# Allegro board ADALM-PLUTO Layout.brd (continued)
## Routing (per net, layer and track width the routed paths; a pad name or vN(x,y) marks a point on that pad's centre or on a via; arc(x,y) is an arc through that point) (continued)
PGND: length 9.8
  TOP w0.305: 102.27,48.02 C181.1 ; C181.1 102.27,49.41 ; C181.1 101.63,48.71 ; 102.46,51.57 D2.2
  TOP w0.406: 102.97,50.87 103.24,51.15 P3.5
  TOP w0.508: 99.2,48.02 E10.2 ; E10.2 100.18,48.87 ; E10.2 101.15,48.02 ; 99.32,51.93 C214.2 100.18,51.13
  TOP w0.635: R58.2 103.1,47.32
  vias: v1(98.02,51.76) v1(98.91,48.89) v1(99.41,50.75) v1(100.81,50.75) v1(101.34,49.2) v1(102.33,50.87) v1(102.72,47.7) v1(103.6,55.06)
VCCPINT: length 38.6
  TOP w0.305: U4.G6 v2(54.73,35.35) ; U4.H5 v2(54.73,36.15) ; 77.95,13.92 UNK1P0V.1 ; UNK1P0V.1 77.95,15.44 ; UNK1P0V.1 77.19,14.68 ; UNK1P0V.1 78.71,14.68 ; U4.E10 v2(57.13,31.35) ; U4.G10 v2(55.53,31.35) ; U4.K5 v2(52.33,36.15) ; U4.F9 v2(56.33,32.15) ; U4.L10 v2(51.53,31.35) ; U4.J10 v2(53.13,31.35)
  TOP w0.508: 56.43,22.69 C68.1 56.99,22.13
  TOP w0.762: 78.62,17.79 C19.1 77.57,16.89 ; 81.6,17.79 C17.1 ; C17.1 83.7,17.79 ; C17.1 82.65,16.89 ; C71.1 59.9,22.55 ; C71.1 58.65,23.61 ; C71.1 57.39,22.55 ; C64.1 63.16,22.49 ; C64.1 60.64,22.49 ; C64.1 61.9,23.54 ; 85.19,16.89 C21.1 ; C21.1 84.14,17.79 ; C21.1 86.24,17.79 ; 80.11,16.89 C20.1 ; C20.1 81.16,17.79 ; C20.1 79.06,17.79
  TOP w1.524: 85,14.04 L4.2 85.99,16.14
  BOTTOM w0.305: v1(82.52,16.46) 84.03,16.46 R7.2
  BOTTOM w0.406: C72.1 51.53,31.84 v2(51.53,31.35) ; v2(55.53,31.35) 55.53,31.85 C74.1 55.73,32.05 56.23,32.05 v2(56.33,32.15) 56.33,32.76 C75.1 ; C70.1 54.73,35.35 v2(54.73,35.35) 54.73,36.15 v2(54.73,36.15) ; C66.1 53.83,30.64 v2(53.13,31.35) ; C73.1 52.33,36.15 v2(52.33,36.15)
  vias: v1(57.2,22.87) v1(57.2,22.11) v1(60.25,22.87) v1(60.25,22.11) v1(63.42,22.87) v1(63.42,22.11) v1(77.95,16.46) v1(77.95,15.69) v1(78.71,16.46) v1(78.71,15.69) v1(79.47,16.46) v1(79.47,15.69) v1(80.24,16.46) v1(80.24,15.69) v1(81,16.46) v1(81,15.69) v1(81.76,16.46) v1(81.76,15.69) v1(82.52,15.69)
VCCPLL: length 18.1
  TOP w0.305: U4.F5 v2(56.33,36.15)
  BOTTOM w0.152: 58.73,36.15 58.34,35.75 56.73,35.75 56.34,36.15 v2(56.33,36.15) 56.33,36.15 56.73,36.55 58.33,36.55 58.73,36.15
  BOTTOM w0.508: 58.73,36.15 C178.1 59.54,36.25 60.63,36.25 61.14,36.75 61.14,37.15 61.74,37.75 62.44,37.75 62.74,37.45
  BOTTOM w0.635: 62.74,37.45 65.28,37.45 C85.1 65.89,37.55 67.54,37.55 68.29,36.8 E1.2
VDD33_USB: length 3
  TOP w0.305: v1(80.36,25.35) 79.73,25.35 79.6,25.48 U15.20
  BOTTOM w0.508: v1(80.36,25.35) 79.86,24.84 C165.1
VDD_INTERFACE: length 10.2
  TOP w0.305: C33.1 32.29,16.08 C32.1 ; C33.1 32.7,17.09 ; C33.1 32.29,17.55 ; U5.H12 28.74,27.23 v2(28.83,27.14) 28.84,27.13 C43.1 C45.1
  TOP w0.635: E4.2 34.23,14 ; E4.2 32.27,14 ; E4.2 33.25,14.86 ; 33.06,15.95 C32.1 32.42,15.25
  BOTTOM w0.305: C44.1 28.83,27.26 28.83,27.26 v2(28.83,27.14) 28.83,26.65 C38.1
  vias: v1(32.99,16.84) v1(33.37,15.95) v1(33.37,15.31) v1(33.63,16.84) v1(34.01,15.95) v1(34.01,15.31) v1(34.26,16.84)
VDDA1P1_RX_VCO: length 3.1
  TOP w0.305: U5.G3 v2(29.14,35.28) ; U5.G2 v2(29.14,36.08)
  BOTTOM w0.305: v2(29.15,35.28) C125.2 29.63,35.94 R51.2 29.73,36.08 v2(29.14,36.08)
VIN: length 59.9
  TOP w0.152: U6.28 v2(91.8,40.71)
  TOP w0.203: U14.10 40.72,58.56 ; R222.1 41.06,60.41 40.79,60.68 39.17,60.68 38.92,60.44 R221.1
  TOP w0.254: 91.79,48.84 92.68,48.84 93.19,48.33 93.57,48.33
  TOP w0.305: 91.16,16.55 C8.1 91.62,16.14 ; 93.29,64.45 U8.9 93.7,63.86 ; 91.75,19.16 U3.13 92.5,19.6 ; U15.21 v1(79.86,25.98) 80.8,25.98 C164.1 ; R221.1 38.92,58.48 v1(38.96,58.44) 39.08,58.56 C62.2 40.72,58.56 ; 89.76,41.48 90.02,41.73 90.21,41.73 U6.25 90.3,41.12 ; 91.19,18.6 U3.12 90.76,17.85 ; 90.29,64.46 U8.15 ; U6.15 90.8,47.42 ; 90.8,41.12 U6.26 ; 89.78,47.04 89.98,46.84 90.18,46.84 U6.16 90.3,47.42 ; U6.27 91.3,40.98 v1(91.03,40.71) ; 92.99,19.57 R1.2 ; R1.2 93.9,19.57 ; R1.2 93.44,19.16 ; 93.57,48.33 94.65,48.33 R56.1 ; 89.29,63.86 U8.16 89.79,64.46 ; C169.1 51.41,12.65 ; C169.1 50.87,13.16 ; C169.1 50.87,12.14 ; 91.3,47.56 U6.14 ; U8.10 92.79,64.44
  TOP w0.508: C185.1 84.17,64.54 ; C185.1 83.12,63.64 ; C185.1 85.23,63.64 ; DS1.A v1(106.78,19.29) ; C184.1 87.9,63.64 ; C184.1 85.79,63.64 ; C184.1 86.84,64.54 ; DS2.A v1(106.91,10.91)
  TOP w0.635: 91.98,16.39 C9.1 ; C9.1 92.68,17.03 ; C9.1 93.38,16.39
  TOP w0.762: C138.1 89.95,51.32 ; C138.1 89.95,49.92 ; C138.1 90.59,50.62 ; C137.1 90.21,38.62 ; C137.1 90.84,37.92 ; C137.1 90.21,37.22 ; 89.95,48.14 C136.1 ; C136.1 90.59,48.84 ; C136.1 89.95,49.54 ; 90.21,39 C135.1 ; C135.1 90.84,39.7 ; C135.1 90.21,40.4 ; 52.8,12.85 E2.1
  TOP w1.016: 94.97,17.55 C11.1 93.91,16.65
  BOTTOM w0.254: U9.10 66.46,58.12 C188.1 C215.1
  BOTTOM w0.305: 28.24,13.55 E7.1 29.22,12.7 ; v1(68.17,55.19) 66.46,56.91 C215.1 ; R6.1 v1(92.94,18.11) ; 28.75,14.2 C123.1 28.21,13.69
  BOTTOM w0.406: R59.2 92.42,38.94 v1(91.67,38.94)
  vias: v1(29.18,13.79) v1(29.56,13.03) v1(52.04,12.52) v1(52.04,11.76) v1(52.93,12.52) v1(52.93,11.76) v1(83.35,64.94) v1(83.67,65.35) v1(83.98,64.94) v1(84.3,65.35) v1(84.62,64.94) v1(84.94,65.35) v1(85.25,64.94) v1(85.57,65.35) v1(85.89,64.94) v1(86.21,65.35) v1(86.52,64.94) v1(86.84,65.35) v1(87.16,64.94) v1(87.48,65.35) v1(87.79,64.94) v1(90.4,51.51) v1(90.4,37.03) v1(90.4,36.4) v1(90.78,50.87) v1(90.78,50.24) v1(90.78,49.6) v1(91.03,38.94) v1(91.03,38.3) v1(91.03,37.67) v1(91.03,37.03) v1(91.03,36.4) v1(91.03,17.47) v1(91.03,16.84) v1(91.41,50.87) v1(91.41,50.24) v1(91.41,49.6) v1(91.67,38.3) v1(91.67,37.67) v1(91.67,37.03) v1(91.67,36.4) v1(91.67,17.47) v1(91.67,16.84) v1(92.3,18.11) v1(92.3,17.47) v1(92.94,17.47) v1(93.57,18.11) v1(93.57,17.47) v1(94.21,18.11) v1(94.84,18.11)
VIN_5V_USB_DATA: length 12.2
  TOP w0.305: 93.06,60.14 92.99,60.22 92.79,60.7 U8.7 ; C210.1 96.33,60.94 ; C210.1 94.63,60.94 ; C210.1 95.48,60.14 ; 93.29,60.43 U8.8 93.92,61
  TOP w0.508: 103.1,41.22 F1.2 102.57,40.61
  TOP w0.635: E3.1 102.46,39.87 ; E3.1 103.44,39.02 ; E3.1 102.3,39.19 100.65,39.19 C183.1
  BOTTOM w0.406: v1(103.75,40.72) v1(103.75,40.09) 103.64,40.21 R88.1
  vias: v1(97.07,61.06) v1(97.07,60.43) v1(97.7,61.06) v1(97.7,60.43) v1(98.34,61.06) v1(98.34,60.43) v1(103.72,38.83) v1(103.75,41.36) v1(103.75,39.45) v1(104.39,41.36) v1(104.39,40.72) v1(104.39,40.09) v1(104.39,39.45) v1(104.36,38.83)
VIN_5V_USB_POWER: length 27.9
  TOP w0.254: 102.08,42.37 U16.A1 102.46,42.75
  TOP w0.305: 89.38,61 U8.1 89.79,60.42 ; 104.18,42.55 C182.1 ; C182.1 104.18,43.95 ; C182.1 103.54,43.25 ; 90.02,60.27 90.29,60.55 U8.2
  TOP w0.635: C209.1 89.09,59.98 ; C209.1 89.09,58.28 ; C209.1 89.89,59.13 ; 89.09,57.95 C212.1 89.89,57.1 ; 90.82,57.18 E9.1 ; E9.1 91.79,58.04 ; E9.1 92.77,57.18
  BOTTOM w0.305: v1(85.44,56.21) 84.05,57.6 74.52,57.6 73.9,56.98 R80.1 ; R70.1 89.76,59.59 v1(90.32,59.03)
  vias: v1(90.32,58.39) v1(90.96,59.03) v1(90.96,58.39) v1(91.59,59.03) v1(91.59,58.39) v1(102.97,45.16) v1(102.97,44.27) v1(103.6,45.16) v1(103.6,44.27) v1(104.24,45.16) v1(104.24,44.27)
1P3_SUPPLY_A: length 79.2
  TOP w0.203: U7.9 42.22,14.51 42.06,14.68 41.69,14.68 41.57,14.56
  TOP w0.305: U7.13 39.35,13.29 ; U7.13 38.57,12.86 ; U7.13 U7.14 38.57,12.21 ; U5.F2 v2(30.74,36.08) ; U5.E2 v2(31.54,36.08) ; U5.B10 v2(33.94,28.88) ; U5.B9 v2(33.94,29.68) ; C18.1 41.96,16.14 ; C18.1 41.04,16.14 ; C18.1 41.5,15.73 ; 40.23,15.73 C16.1 ; C16.1 39.77,16.14 ; C16.1 40.69,16.14 ; 42.39,16.33 UNK1P3V_A.1 43.15,15.57 ; U7.12 40.27,14.56 ; U7.12 U7.11 ; U7.12 39.84,13.78 ; 41.57,14.56 U7.10 U7.11 ; U7.11 40.92,14.56 ; U5.J3 v2(27.55,35.28) ; U5.K3 v2(26.74,35.28)
  TOP w0.635: 38.01,15.81 C14.1 ; C14.1 39.41,15.81 ; C14.1 38.71,15.17 ; 37.88,13.6 C15.1 ; C15.1 37.88,15 ; C15.1 38.52,14.3
  BOTTOM w0.305: 31.46,36.08 v2(30.74,36.08) ; 31.46,36.08 31.33,36.2 C23.1 31.33,36.96 31.84,37.47 C28.1 ; 31.46,36.08 v2(31.54,36.08) ; v2(27.55,35.28) 27.33,35.5 C39.1 27.33,36.46 27.45,36.58 ; v2(33.94,28.88) 33.86,28.96 C40.1 33.86,29.6 v2(33.94,29.68) ; C29.1 26.26,36.57 C24.1 26.49,35.64 26.49,35.53 v2(26.74,35.28)
  BOTTOM w0.406: v2(33.94,28.88) 33.95,28.88 C35.1
  BOTTOM w0.508: C28.1 31.84,44.91 31.47,45.29 30.71,45.29 30.33,44.9 v1(30.33,43.15) v1(30.33,42.24) ; v1(26.01,42.29) v1(26.01,43.05) 26.01,43.79 25.53,44.26 24.73,44.26 24.36,43.89 24.36,39.82 23.47,38.94 23.47,37.92 24.5,36.88 C29.1 ; v1(29.06,42.24) v1(29.06,43.13) 29.06,44.9 28.55,45.41 27.91,45.41 27.45,44.95 C34.1 27.45,36.58
  BOTTOM w0.635: v1(42.14,20.14) v1(41.25,20.14) 39.98,20.14 39.6,20.52 39.6,25.52 arc(39.54,25.83) 39.36,26.09 36.57,28.88 C35.1
  vias: v1(37.82,15.19) v1(37.84,15.87) v1(38.76,14.96) v1(38.83,14.3) v1(39.6,16.08) v1(39.6,15.19) v1(40.87,16.08) v1(42.14,16.08)
1P3_SUPPLY_B: length 119.6
  TOP w0.305: U5.F12 v2(30.74,27.28) ; v1(39.93,34.01) 40.64,34.72 41.35,34.72 41.85,34.22 C166.2 41.92,33.96 L1.1 ; U5.A9 34.34,30.1 v2(34.75,30.5) ; U5.D2 v2(32.34,36.08) ; U5.E3 v2(31.54,35.28) ; v1(21.14,27.63) 21.14,27.6 20.78,27.24 C129.2 20.97,26.86 arc(21.71,27.01) 22.34,27.43 L8.1 ; U5.A10 34.71,29.64 v2(34.75,29.64) ; U5.M10 v2(25.14,28.88) ; v1(36.78,25.17) 36.17,25.78 36.17,26.74 36.59,27.17 C193.2 36.59,28.11 L7.1 ; v1(21.14,33.09) 20.78,33.45 C194.2 21.31,33.69 arc(21.72,33.61) 22.07,33.38 L9.1 ; U5.D3 v2(32.34,35.28) ; U5.M9 v2(25.14,29.68) ; U5.K4 v2(26.74,34.48)
  BOTTOM w0.305: U1.13 24.02,57.62 ; U1.13 24.02,56.84 U1.14 24.67,57.29 24.1,57.86 ; U1.13 23.59,56.84 ; 21.17,54.7 C6.1 ; C6.1 21.57,55.15 ; C6.1 21.17,55.61 ; C27.1 35.84,31.4 C31.1 ; v2(25.14,28.88) 25.11,28.92 C191.1 23.24,28.92 ; 23.24,28.92 23.22,28.92 C192.1 ; 23.24,28.92 23.16,28.83 ; 22.32,55.92 U1.12 23.09,56.35 ; C5.1 21.17,54.34 ; C5.1 21.57,53.88 ; C5.1 21.16,53.43 ; 22.31,53.97 U1.9 23.09,53.54 ; C36.1 24.53,33.8 25.25,33.8 25.62,34.17 C41.1 26.01,34.18 26.45,34.18 v2(26.74,34.48) ; C30.1 30.73,25.95 C26.1 30.73,27.26 v2(30.74,27.28) ; 22.32,55.27 U1.11 ; 22.31,54.62 U1.10
  BOTTOM w0.381: v2(34.75,29.64) v2(34.75,30.5) C27.1
  BOTTOM w0.406: v2(31.54,35.28) v2(32.34,35.28) 32.34,35.37 ; 32.34,35.37 v2(32.34,36.08) ; 32.34,35.37 32.47,35.49 C42.1 33.83,35.49 C37.1
  BOTTOM w0.508: v1(21.05,20.65) v1(21.82,20.65) 25.37,24.2 30.2,24.2 30.9,24.9 C30.1 ; v1(14.09,36.18) v1(14.91,36.18) 16.73,34.36 24.02,34.36 24.48,33.9 C36.1 ; C31.1 36.36,31.38 36.75,31.77 36.75,36.58 34.01,39.32 v1(34.01,42.36) v1(34.01,43.2) ; v1(37.06,30.68) 37.56,31.19 38.12,31.19 C167.1 ; v2(25.14,28.88) 25.14,29.68 v2(25.14,29.68) ; 23.16,28.83 23.16,27.2 20.29,24.33 18.13,24.33 16.82,25.65 v1(14.7,25.65) v1(14.06,25.65) ; C155.1 20.88,30.19 20.17,29.47 20.17,27.09 19.55,26.47 v1(18.33,26.47) ; v1(33.24,43.19) v1(33.24,42.39) 33.24,38.94 35.41,36.78 35.41,35.63 35.14,35.37 C37.1
  BOTTOM w0.635: 22.02,58.72 C3.1 ; C3.1 22.87,57.92 ; C3.1 23.72,58.71 ; v1(21.14,27.63) 21.14,30.01 C155.1 21.14,30.52 v1(21.14,33.09) ; C4.1 21.29,53.06 ; C4.1 21.92,52.36 ; C4.1 21.28,51.66
  vias: v1(21.11,50.82) v1(21.12,50.16) v1(21.12,49.46) v1(21.32,56.37) v1(21.33,57.73) v1(21.33,57.08) v1(21.74,50.82) v1(21.76,50.16) v1(21.76,49.46) v1(21.99,57.73) v1(21.99,57.07) v1(21.96,56.37)
1P8V_CLK: length 10.7
  TOP w0.305: 45.82,16.33 UNK1P8V_CLK.1 45.06,15.57 ; 47.61,15.71 U12.1 48.29,16.12 ; 46.07,15.54 C170.1 ; C170.1 46.58,16.07 ; C170.1 47.09,15.54
  BOTTOM w0.305: v1(17.78,6.74) 17.75,6.77 v1(17.75,7.31) 17.75,7.73 C121.1 17.19,8.24 C122.1 14.02,8.24 Y3.4 ; R101.1 v1(6.32,12.11)
  vias: v1(46.33,16.33) v1(46.96,16.33) v1(47.72,16.33)
3P3V: length 102.9
  TOP w0.305: U5.B8 v2(33.94,30.48)
  TOP w0.508: E8.1 18.55,17.19 C199.1 19.32,17.13 v1(19.4,17.22)
  L6_SIG w0.305: v1(30.01,59.32) 27.79,57.1 24.23,57.1 18.4,51.27 18.4,42.89 18.52,42.77 18.52,36 19.41,35.12 19.41,27.29 19.4,27.28 v1(19.4,17.22)
  BOTTOM w0.127: v2(33.94,30.48) 33.52,30.06 32.88,30.06 32.74,29.92 32.74,26.62 33.37,25.98
  BOTTOM w0.305: VDD_GPO.1 40.61,63.95 40.61,60.65 39.72,59.76 30.45,59.76 v1(30.01,59.32) ; U11.1 21.87,10.98 C198.1 ; v2(33.94,30.48) 33.94,31.37 C203.1
  BOTTOM w0.508: 33.37,25.98 33.37,22.68 28.8,18.11 20.29,18.11 v1(19.4,17.22) 19.02,16.84 19.02,13.28 19.77,12.53 C198.1
3P3V_CLK: length 12.6
  TOP w0.305: v1(10.75,10.98) C201.1 11.89,11.49 U17.11 ; E8.2 15.34,18.17 ; E8.2 14.49,17.19 ; E8.2 15.34,16.21 ; v1(20.42,11) 19.93,11.48 C202.1 19.29,11.49 U17.2 ; 14.16,14.93 R85.1 ; R85.1 14.72,15.49 ; R85.1 14.16,16.05 ; 14.06,16.97 C200.1 13.55,16.44 ; 16.59,14.09 U17.6 17.54,14.55
  vias: v1(15.44,15.01) v1(15.75,15.52) v1(15.74,14.43) v1(16,15.01)
AD9363_AUXADC: length 50
  TOP w0.127: U5.L5 v2(25.95,32.88)
  L6_SIG w0.127: v2(25.95,32.88) U5.L5 26.94,33.28 27.14,33.48 27.14,33.98 27.27,34.1 27.77,34.1 27.95,34.28 27.95,37.18 28.42,37.66 28.42,48.57 29.99,50.14 29.99,57.78 35.53,63.32 35.53,66.49 36.04,67 42.64,67 ADC.1
  BOTTOM w0.127: C207.2 25.37,32.04 25.95,32.61 v2(25.95,32.88)
AD9363_AUXDAC1: length 117.9
  TOP w0.127: 38.61,35.07 38.76,35.07 40.99,37.31 40.99,46.35 40.79,46.56 v1(40.54,46.56) ; 38.61,35.07 36.15,35.07 35.85,34.77 35.03,34.77 34.52,35.28 34.14,35.28 33.93,35.07 U5.B3 ; 38.61,35.07 38.61,35.08 C206.1
  L5_SIG w0.127: v1(12.55,4.52) 12.16,4.52 7.72,8.96 7.72,16.08 9.62,17.98 9.62,24.2 11.66,26.24 11.66,26.31 11.91,26.56 11.98,26.56 16.74,31.32 16.74,34.87 17.37,35.51 17.37,39.44 24.48,46.56 v1(40.54,46.56)
  L6_SIG w0.127: v1(40.54,46.56) 40.16,46.56 38.99,47.72 38.99,51.84 37.29,53.54 33.86,53.54 31.98,55.42 31.98,58.75 34.39,61.16 37.31,61.16 37.92,61.77 37.92,64.11 DAC1.1
  BOTTOM w0.127: R5.1 13.79,6.2 13.74,6.25 13.74,5.33 12.93,4.52 v1(12.55,4.52)
AD9363_AUXDAC2: length 45
  TOP w0.127: U5.C3 33.15,35.28 33.76,35.28 33.95,35.47 33.95,36 v2(33.98,36.04)
  L6_SIG w0.127: v2(40.54,45.97) 40.51,45.97 40.49,45.95 40.21,45.95 38.8,47.35 arc(38.75,47.43) 38.73,47.51 38.73,51.7 38.71,51.76 37.23,53.24 arc(37.18,53.27) 37.12,53.29 33.82,53.29 arc(33.76,53.3) 33.71,53.33 31.77,55.27 arc(31.74,55.32) 31.72,55.39 31.72,58.93 arc(31.74,59) 31.77,59.05 35.41,62.68 DAC2.1
  BOTTOM w0.127: v2(33.98,36.04) 34,36.06 34,36.97 C208.1 33.06,37.86 32.48,38.43 32.48,44.02 33.37,44.9 39.37,44.9 40.44,45.97 v2(40.54,45.97)
AD9363_GPO_0: length 51
  TOP w0.127: v1(40.49,49.1) 40.69,49.1 41.71,48.08 41.71,47.08 42.01,46.77 42.01,36.89 39.18,34.06 37.03,34.06 35.05,32.08 33.94,32.08 U5.B7
  L6_SIG w0.127: GPO0.1 41.35,59.61 34.87,59.61 32.99,57.73 32.99,55.85 34.28,54.56 37.71,54.56 38.13,54.14 38.47,53.79 38.47,53.79 38.83,53.44 39.92,52.35 40,52.26 40,49.32 40.23,49.1 v1(40.49,49.1)
AD9363_GPO_1: length 48.9
  TOP w0.127: v1(40.54,48.46) 40.66,48.46 41.45,47.67 41.45,46.97 41.76,46.67 41.76,36.99 39.08,34.31 36.68,34.31 35.24,32.88 33.94,32.88 U5.B6
  L6_SIG w0.127: GPO1.1 41.88,61.54 40.35,60.01 34.76,60.01 32.74,57.99 32.74,55.74 34.18,54.3 37.6,54.3 37.95,53.96 38.37,53.54 39.01,52.9 39.69,52.22 39.75,52.16 39.75,48.74 40.03,48.46 v1(40.54,48.46)
AD9363_GPO_2: length 46.2
  TOP w0.127: U5.B5 33.94,33.68 35.58,33.68 36.47,34.57 38.97,34.57 41.5,37.1 41.5,46.56 41.2,46.87 41.2,47.37 40.74,47.83 v1(40.54,47.83)
  L6_SIG w0.127: v1(40.54,47.83) 40.03,47.83 39.5,48.36 39.5,52.05 39.41,52.14 39.33,52.22 37.77,53.78 37.5,54.05 34.07,54.05 32.48,55.64 32.48,58.24 34.66,60.41 38.21,60.41 39.34,61.54 GPO2.1
AD9363_GPO_3: length 47.8
  TOP w0.127: U5.B4 33.93,34.47 35.96,34.47 36.32,34.82 38.86,34.82 41.25,37.2 41.25,46.46 40.94,46.76 40.94,46.96 40.71,47.19 v1(40.54,47.19)
  L6_SIG w0.127: GPO3.1 38.22,64.1 38.22,61.56 37.47,60.81 34.55,60.81 32.23,58.49 32.23,55.53 33.97,53.79 37.39,53.79 37.59,53.6 39.15,52.04 39.24,51.95 39.24,47.98 40.03,47.19 v1(40.54,47.19)
ADP2114_VIN: length 20.7
  TOP w0.203: 93.57,40.97 93.3,41.24 U6.31
  TOP w0.254: v1(95.98,48.46) 95.67,48.46 R56.2
  TOP w0.305: v1(95.35,44.14) 95.23,44.02 U6.4 ; U6.10 93.3,47.27 93.6,47.57 95.24,47.57 C141.1 ; v1(95.98,48.46) 96.18,48.27 96.18,46.99 C141.1 ; 93.57,40.97 93.95,40.59 v1(94.71,40.59) ; U6.8 95.21,46.02 C141.1
  L5_SIG w0.305: v1(94.71,40.59) 95.22,40.59 96.1,41.46 96.1,43.02 95.35,43.76 v1(95.35,44.14) 95.68,44.14 95.98,44.45 v1(95.98,48.46)
CLK_SOURCE_SEL: length 7.5
  TOP w0.305: R103.1 14.4,4.59 14.4,6.49 Q3.1 v1(11.72,6.51)
  BOTTOM w0.305: Q2.1 10.71,6.41 R102.1 10.83,6.51 v1(11.72,6.51)
COMP_1P8V: length 2.8
  TOP w0.305: v1(95.35,42.87) 95.2,43.02 U6.2
  BOTTOM w0.508: C142.2 R60.1 95.48,42.75 v1(95.35,42.87)
COMP_1P35V: length 3.1
  TOP w0.305: U6.7 96.1,45.52 C143.2 C144.1
CTRL_IN0: length 52.1
  TOP w0.102: U5.C5 v2(33.14,33.68) ; U4.F13 v2(56.33,28.95)
  L6_SIG w0.114: v2(33.14,33.68) 33.15,33.68 33.55,34.08 33.55,34.68 33.35,34.88 31.35,34.88 30.34,33.88 30.34,32.68 30.15,32.48 28.65,32.48 27.95,31.78 27.95,24.43 30.07,22.3 38.54,22.3 38.66,22.42 39.01,22.42 39.13,22.3 41.1,22.3 41.22,22.42 41.53,22.42 41.65,22.3 53.49,22.3 56.72,25.53 56.72,26.91 56.33,27.31 v2(56.33,28.95)
CTRL_IN1: length 47.2
  TOP w0.102: v2(56.33,26.55) 56.33,28.14 55.93,28.54 U4.F14 ; U5.C6 v2(33.14,32.88)
  L6_SIG w0.114: v2(56.33,26.55) 56.33,25.74 53.27,22.68 30.33,22.68 28.35,24.66 28.35,30.68 28.74,31.07 28.74,31.58 28.84,31.68 29.35,31.68 29.71,32.05 30.11,32.05 30.82,32.75 30.82,33.15 31.75,34.08 32.55,34.08 32.75,33.88 32.75,33.28 33.14,32.89 v2(33.14,32.88)
CTRL_IN2: length 37.8
  TOP w0.102: v2(55.53,27.35) U4.G15 ; U5.D6 v2(32.34,32.88)
  L6_SIG w0.114: v2(55.53,27.35) 54.96,26.78 54.96,26.37 54.66,26.07 54.06,26.07 52.19,24.2 40.55,24.2 40.54,24.19 40.23,24.19 40.21,24.2 39.31,24.2 39.24,24.14 38.89,24.14 38.82,24.2 31.82,24.2 31.25,24.77 31.25,24.94 31.22,24.96 31.22,25.27 31.25,25.3 31.25,25.57 30.05,26.77 30.05,28.04 29.55,28.54 29.55,30.68 29.75,30.88 30.15,30.88 30.35,31.08 30.35,31.48 31.22,32.35 31.61,32.35 32.14,32.88 v2(32.34,32.88)
CTRL_IN3: length 41.3
  TOP w0.102: U4.F15 55.93,26.95 v2(55.53,26.55) ; U5.D5 v2(32.34,33.68)
  L6_SIG w0.114: v2(32.34,33.68) U5.D5 31.34,33.28 31.12,33.05 31.12,32.65 30.17,31.7 29.76,31.7 29.55,31.48 29.55,31.08 29.35,30.88 28.95,30.88 28.75,30.68 28.75,28.17 29.25,27.67 29.25,25.28 30.71,23.82 52.61,23.82 53.98,25.18 54.97,25.18 55.53,25.75 v2(55.53,26.55)
DDR3_A0: length 30.1
  TOP w0.165: U4.P1 49.03,39.45 48.41,39.45 47.5,40.36 47.5,40.36 47.01,40.85 v2(43.92,40.85) ; U2.N3 51.22,54.27 v2(51.22,54.27)
  L6_SIG w0.165: v2(43.92,40.85) 43.32,41.45 43.32,42.04 43.52,42.23 43.91,42.23 44.11,42.43 44.11,42.71 43.91,42.91 43.52,42.91 43.32,43.1 43.32,43.38 43.52,43.58 43.91,43.58 44.11,43.78 44.11,44.06 43.91,44.25 43.52,44.25 43.32,44.45 43.32,47.48 46.51,50.67 49.02,50.67 49.41,51.07 49.41,51.87 51.22,53.68 v2(51.22,54.27)
  BOTTOM w0.165: v2(51.22,54.27) 51.62,54.67 51.62,56.16 R16.1
DDR3_A1: length 33.2
  TOP w0.165: v2(43.92,41.65) 46.87,41.65 48.57,39.95 49.33,39.95 U4.N1 ; U2.P7 49.83,51.66 v2(48.03,51.66)
  L6_SIG w0.165: v2(43.92,41.65) 44.41,41.16 44.41,39.66 44.21,39.46 43.61,39.46 42.51,40.56 42.51,48.17 42.72,48.38 42.72,48.78 43.07,49.13 43.47,49.13 43.67,49.33 43.67,49.61 43.4,49.88 43.4,50.16 43.6,50.35 43.88,50.35 44.15,50.08 44.43,50.08 44.62,50.28 44.62,50.56 44.35,50.83 44.35,51.11 44.55,51.31 44.83,51.31 45.1,51.03 45.38,51.03 46,51.66 v2(48.03,51.66)
  BOTTOM w0.165: v2(48.03,51.66) 47.45,51.66 R22.1
DDR3_A2: length 35.7
  TOP w0.165: U2.P3 v2(50.42,54.27) ; U4.M1 51.13,39.75 v2(49.93,40.95)
  L5_SIG w0.165: v2(50.42,54.27) 50.02,53.87 48.5,53.87 45.83,51.2 45.83,39.25 47.59,37.49 47.87,37.49 48.03,37.65 48.03,38.75 48.23,38.95 48.53,38.95 48.73,38.75 48.73,37.75 48.93,37.55 49.13,37.55 49.53,37.95 49.53,38.95 49.93,39.35 49.93,39.65 49.23,40.35 49.23,40.65 49.53,40.95 v2(49.93,40.95)
  BOTTOM w0.165: v2(50.42,54.27) 50.02,53.87 49.3,53.87 48.61,54.56 47.45,54.56 R17.1
DDR3_A3: length 31.5
  TOP w0.165: U4.M4 v2(50.73,36.95) ; U2.N2 v2(51.22,55.07)
  L5_SIG w0.165: v2(50.73,36.95) 51.02,36.95 51.13,37.06 51.13,37.97 51.48,38.33 51.48,38.63 51.28,38.83 50.9,38.83 50.73,39 50.73,42.75 50.53,42.95 49.93,42.95 49.53,43.35 49.53,44.55 49.71,44.73 50.13,44.73 50.33,44.93 50.33,45.21 50.13,45.4 49.73,45.4 49.53,45.6 49.53,45.88 49.73,46.08 50.13,46.08 50.33,46.27 50.33,46.55 50.13,46.75 49.73,46.75 49.53,46.95 49.53,47.23 49.73,47.42 50.13,47.42 50.33,47.62 50.33,48.06 50.12,48.27 49.92,48.27 49.73,48.46 49.73,49.56 50.04,49.87 50.64,49.87 50.82,50.04 50.82,51.73 51,51.92 51.51,51.92 51.69,52.09 51.69,52.58 51.85,52.74 52.59,52.74 52.75,52.9 52.75,53.12 52.59,53.28 51.85,53.28 51.69,53.44 51.69,53.74 51.85,53.9 52.6,53.9 52.76,54.06 52.76,54.28 52.6,54.44 51.65,54.44 51.46,54.63 51.46,54.83 v2(51.22,55.07)
  BOTTOM w0.165: R23.1 50.82,56.16 50.82,55.2 50.94,55.07 v2(51.22,55.07)
DDR3_A4: length 26.7
  TOP w0.165: v2(47.33,38.65) 48.23,37.75 49.13,37.75 U4.P3 ; v2(50.42,50.27) U2.P8
  L6_SIG w0.165: v2(50.42,50.27) 50.83,49.86 50.83,48.28 50.62,48.07 49.82,48.07 46.41,44.66 46.41,41.76 46.71,41.46 48.91,41.46 49.13,41.25 49.13,40.75 48.84,40.46 48.04,40.46 47.81,40.23 47.81,39.66 47.61,39.46 46.71,39.46 46.51,39.26 46.51,38.46 46.72,38.25 46.93,38.25 v2(47.33,38.65)
  BOTTOM w0.165: R18.1 47.64,50.67 50.02,50.67 v2(50.42,50.27)
DDR3_A5: length 24
  TOP w0.165: U2.P2 v2(50.42,55.07) ; v2(49.11,36.96) U4.P4
  L5_SIG w0.165: v2(49.11,36.96) 49.5,37.35 50.13,37.35 50.33,37.55 50.33,38.05 50.33,38.05 50.45,38.17 50.45,38.73 50.33,38.85 50.33,42.35 50.13,42.55 49.73,42.55 49.13,43.15 49.13,48.16 49.33,48.36 49.33,49.78 50.43,50.88 50.43,51.98 51.23,52.78 51.23,53.56 50.82,53.97 50.82,54.67 v2(50.42,55.07)
  BOTTOM w0.165: v2(50.42,55.07) 50.14,55.07 50.02,55.2 50.02,56.16 R24.1
DDR3_A6: length 26.8
  TOP w0.165: U4.P5 49.13,36.15 47.13,36.15 v2(46.72,36.55) ; U2.R8 49.62,49.47 48.81,49.47 v2(48.01,48.67)
  L6_SIG w0.165: v2(46.72,36.55) 44.91,38.36 44.91,38.86 45.21,39.16 45.21,44.26 44.21,45.26 44.21,47.07 44.82,47.67 45.1,47.67 45.37,47.4 45.65,47.4 45.84,47.6 45.84,47.88 45.61,48.11 45.61,48.47 46.01,48.87 46.29,48.87 46.42,48.74 46.42,47.96 46.63,47.76 47.13,47.76 47.33,47.96 47.33,48.26 47.09,48.49 47.09,48.87 47.29,49.07 47.62,49.07 v2(48.01,48.67)
  BOTTOM w0.165: v2(48.01,48.67) 48.52,48.17 48.63,48.17 R19.1
DDR3_A7: length 30.3
  TOP w0.165: U2.R2 v2(49.62,55.07) ; U4.M5 v2(50.73,36.15)
  L5_SIG w0.165: v2(50.73,36.15) 50.33,35.75 49.03,35.75 48.63,36.15 47.73,36.15 46.57,37.3 45.67,37.3 45.02,37.95 45.02,51.58 48.82,55.37 49.31,55.37 v2(49.62,55.07)
  BOTTOM w0.165: v2(49.62,55.07) 49.33,55.36 48.63,55.36 48.12,55.87 R25.1
DDR3_A8: length 24.1
  TOP w0.165: v2(46.72,35.75) 47.12,35.35 49.13,35.35 U4.P6 ; v2(48.01,49.47) 48.41,49.87 U2.T8
  L6_SIG w0.165: v2(46.72,35.75) 46.42,36.16 44.51,38.06 44.51,39.16 44.81,39.46 44.81,44.06 43.81,45.06 43.81,47.27 46.01,49.47 v2(48.01,49.47)
  BOTTOM w0.165: R20.1 47.52,48.55 47.52,48.97 v2(48.01,49.47)
DDR3_A9: length 27.7
  TOP w0.165: U4.N4 v2(49.93,36.95) ; v2(49.61,54.27) U2.R3
  L5_SIG w0.165: v2(49.93,36.95) 49.43,36.45 48.93,36.45 48.33,37.05 47.43,37.05 45.43,39.05 45.43,51.36 48.34,54.27 v2(49.61,54.27)
  BOTTOM w0.165: R26.1 47.87,54.94 48.95,54.94 v2(49.61,54.27)
DDR3_A10: length 39.2
  TOP w0.165: v2(53.13,40.35) 53.13,39.35 U4.J1 ; U2.L7 53.21,50.67 v2(52.81,51.07)
  L5_SIG w0.165: v2(52.81,51.07) 53.23,50.66 53.48,50.66 53.63,50.51 53.63,50.1 53.13,49.6 53.13,48.8 52.93,48.6 52.63,48.6 52.43,48.41 52.43,48.13 52.63,47.93 53.43,47.93 53.63,47.73 53.63,47.35 53.43,47.15 52.43,47.15 52.43,47.16 52.13,47.46 51.83,47.46 51.63,47.26 51.63,46.62 51.83,46.41 52.23,46.41 52.43,46.22 52.43,45.94 52.23,45.74 51.83,45.74 51.63,45.54 51.63,45.15 51.92,44.87 52.24,44.87 52.73,45.36 53.03,45.36 53.23,45.16 53.23,44.41 53.1,44.28 52.35,44.28 52.13,44.06 52.13,43.86 52.32,43.67 53.1,43.67 53.32,43.45 53.32,43.22 53.03,42.93 52.73,42.93 52.53,42.74 52.53,42.46 52.73,42.26 52.93,42.26 53.13,42.06 53.13,41.79 52.93,41.59 52.73,41.59 52.32,41.18 52.32,40.36 52.73,39.95 52.73,35.95 52.93,35.75 54.13,35.75 54.33,35.95 54.33,36.25 54.13,36.45 53.68,36.45 53.53,36.6 53.53,39.95 v2(53.13,40.35)
  BOTTOM w0.165: R21.1 51.62,48.28 51.62,50.47 52.22,51.07 v2(52.81,51.07)
DDR3_A11: length 32.7
  TOP w0.165: U4.L2 51.53,38.55 51.53,39.95 50,41.48 48,41.48 v2(47.43,42.05) ; v2(48.02,50.27) 49.62,50.27 U2.R7
  L5_SIG w0.165: v2(48.02,50.27) 47.62,49.87 47.62,49.27 47.81,49.07 48.22,49.07 48.42,48.87 48.42,48.35 48.23,48.16 47.83,48.16 47.63,47.96 47.63,47.52 47.82,47.32 48.53,47.32 48.73,47.12 48.73,46.84 48.53,46.65 47.82,46.65 47.63,46.45 47.63,46.17 47.82,45.97 48.53,45.97 48.73,45.77 48.73,45.5 48.53,45.3 47.82,45.3 47.63,45.1 47.63,44.82 47.82,44.63 48.53,44.63 48.73,44.43 48.73,44.15 48.53,43.95 47.72,43.95 47.53,43.76 47.53,43.45 47.73,43.25 48.43,43.25 48.93,42.75 48.93,41.65 48.73,41.45 48.33,41.45 47.98,41.1 47.98,39.9 47.63,39.55 47.13,39.55 46.81,39.87 46.81,40.72 47.43,41.34 v2(47.43,42.05)
  BOTTOM w0.165: R27.1 47.23,49.49 v2(48.02,50.27)
DDR3_A12: length 30.5
  TOP w0.165: U2.N7 51.22,51.07 v2(51.22,51.07) ; U4.M2 50.75,38.52 50.75,39.34 49.14,40.95 v2(48.43,40.95)
  L6_SIG w0.165: v2(48.43,40.95) 46.32,40.95 46.01,41.26 46.01,45.46 45.81,45.66 45.31,45.66 45.09,45.88 45.09,46.35 45.31,46.57 47.71,46.57 50.03,48.88 50.03,49.19 49.83,49.38 49.51,49.38 49.31,49.58 49.31,49.86 49.51,50.06 49.83,50.06 50.01,50.24 50.01,50.54 50.53,51.06 50.53,51.79 51.5,52.76 51.73,52.76 51.98,52.51 51.98,52.21 51.22,51.44 v2(51.22,51.07)
  BOTTOM w0.165: v2(51.22,51.07) 50.82,50.67 50.82,48.28 R28.1
DDR3_A13: length 30.8
  TOP w0.165: U2.T3 48.82,53.47 v2(48.82,53.47) ; U4.K2 52.33,38.55 52.33,39.89 50.23,41.98 v2(49.93,41.98)
  L5_SIG w0.165: v2(49.93,41.98) 48.83,40.88 48.83,40.15 47.83,39.15 46.72,39.15 46.23,39.65 46.23,45.35 46.63,45.75 46.63,46.15 46.23,46.55 46.23,46.83 46.42,47.03 46.63,47.03 46.83,47.23 46.83,47.5 46.63,47.7 46.42,47.7 46.23,47.9 46.23,48.18 46.42,48.37 46.63,48.37 46.83,48.57 46.83,48.85 46.63,49.05 46.42,49.05 46.23,49.24 46.23,49.52 46.42,49.72 46.63,49.72 46.83,49.92 46.83,50.2 46.63,50.39 46.35,50.39 46.23,50.52 46.23,51.06 48.03,52.86 48.2,52.86 v2(48.82,53.47)
  BOTTOM w0.165: R34.1 48.22,54.07 v2(48.82,53.47)
DDR3_A14: length 35.5
  TOP w0.165: v2(48.43,42.05) 48.87,42.49 50.32,42.49 52.73,40.09 U4.K1 ; v2(48.82,51.07) U2.T7
  L5_SIG w0.165: v2(48.82,51.07) 49.23,50.66 49.23,50.26 48.92,49.95 48.74,49.95 48.53,50.16 48.53,50.46 48.13,50.86 48.13,51.16 48.83,51.86 49.08,51.86 49.59,51.36 49.83,51.36 50.03,51.56 50.03,51.87 49.57,52.32 49.57,52.6 49.73,52.76 50.03,52.76 50.23,52.56 50.5,52.56 50.71,52.78 50.71,53.24 50.5,53.45 49.62,53.45 48.24,52.07 47.84,52.07 47.61,51.84 47.61,51.5 47.38,51.27 47.04,51.27 46.83,51.06 46.83,50.86 47.22,50.47 47.22,45.38 47.03,45.19 46.82,45.19 46.63,45 46.63,44.72 46.82,44.52 47.03,44.52 47.23,44.32 47.23,44.04 47.03,43.85 46.82,43.85 46.63,43.65 46.63,42.55 46.79,42.39 47.07,42.39 47.43,42.75 48.3,42.75 48.43,42.63 v2(48.43,42.05)
  BOTTOM w0.165: R29.1 48.02,51.07 48.46,51.51 48.69,51.51 48.82,51.39 v2(48.82,51.07)
DDR3_BA0: length 34
  TOP w0.165: U2.M2 v2(52.02,55.07) ; U4.M6 v2(50.73,35.35)
  L5_SIG w0.165: v2(52.02,55.07) 52.58,55.63 52.58,57.58 52.77,57.78 53.02,57.78 53.22,57.57 53.22,53.15 53.39,52.98 53.64,52.98 53.87,52.75 53.87,52.3 53.57,51.99 52.14,51.99 51.84,51.69 51.84,50.74 51.62,50.52 51.62,50.04 50.93,49.36 50.93,48.28 50.82,48.17 50.82,44.33 50.6,44.11 50.13,44.11 49.93,43.92 49.93,43.64 50.13,43.44 50.93,43.44 51.13,43.24 51.13,39.55 51.93,38.75 51.93,35.94 51.73,35.75 51.13,35.75 v2(50.73,35.35)
  BOTTOM w0.165: R35.1 52.72,55.57 52.52,55.37 52.32,55.37 v2(52.02,55.07)
DDR3_BA1: length 30.5
  TOP w0.165: U4.R1 48.25,38.95 47.34,39.86 v2(47.34,39.96) ; v2(51.22,50.27) U2.N8
  L6_SIG w0.165: v2(47.34,39.96) 47.34,40.34 47.14,40.53 46.28,40.53 46.11,40.36 46.11,37.76 46.67,37.2 47.05,37.2 47.33,37.47 47.33,37.95 48.23,38.85 48.23,39.57 48.51,39.86 49.11,39.86 49.53,40.27 49.53,42.33 49.33,42.52 47.44,42.52 47.21,42.75 47.21,42.97 47.44,43.2 47.83,43.2 48,43.36 48,43.68 47.76,43.91 47.34,43.91 47.11,44.14 47.11,44.36 47.34,44.59 47.76,44.59 48.13,44.95 48.13,45.78 50,47.65 50.8,47.65 51.22,48.07 v2(51.22,50.27)
  BOTTOM w0.165: R30.1 51.22,47.89 v2(51.22,50.27)
DDR3_BA2: length 28.7
  TOP w0.165: U4.N6 v2(49.93,35.35) ; v2(53.32,52.47) 52.42,53.37 U2.M3
  L6_SIG w0.165: v2(53.32,52.47) 53.61,52.76 53.82,52.76 54.02,52.57 54.02,52.17 53.21,51.36 53.21,48.04 52.33,47.15 52.33,46.65 52.13,46.45 50.7,46.45 49.43,45.18 49.43,44.15 49.63,43.95 49.93,43.95 50.33,44.35 50.63,44.35 51.32,43.66 51.32,41.26 51.72,40.86 51.72,39.96 51.41,39.66 51.02,39.66 50.33,38.97 50.33,36.78 50.57,36.55 50.97,36.55 51.13,36.38 51.13,35.9 50.98,35.75 50.33,35.75 v2(49.93,35.35)
  BOTTOM w0.165: R36.1 52.54,51.69 v2(53.32,52.47)
DDR3_CAS#: length 28.5
  TOP w0.165: v2(53.62,53.46) 54.02,53.86 U2.K3 ; v2(48.21,35.75) U4.R5
  L6_SIG w0.165: v2(48.21,35.75) 48.78,35.18 49.16,35.18 49.43,35.45 49.43,36.02 49.3,36.15 48.93,36.15 48.65,36.43 48.65,37.47 48.81,37.64 49.36,37.64 49.53,37.8 49.53,38.87 50.83,40.17 50.83,43.15 50.52,43.46 49.22,43.46 49.01,43.67 49.01,45.36 50.52,46.87 51.32,46.87 52.73,48.28 52.73,50.36 52.22,50.87 52.22,51.14 52.82,51.74 52.82,52.66 v2(53.62,53.46)
  BOTTOM w0.165: v2(53.62,53.46) 53.63,53.45 53.63,53.01 53.49,52.87 52.94,52.87 R32.1
DDR3_CK_N: length 32.4
  TOP w0.127: v2(53.61,51.07) 54.02,50.67 U2.K7 ; U4.N2 v2(49.93,38.55)
  BOTTOM w0.127: R142.2 53.61,51.66 v2(53.61,51.07) 53.22,50.68 53.22,50.44 53.43,50.23 53.61,50.23 53.94,50.56 54.12,50.56 54.42,50.26 54.42,47.57 55.09,46.9 58.79,46.9 59.14,46.55 59.14,46.06 58.82,45.74 54.85,45.74 54.32,45.21 54.32,44.15 54.06,43.89 51.99,43.89 50.81,45.06 49.92,45.06 49.12,44.26 49.12,43.5 50.95,41.66 50.95,38.95 50.3,38.3 50.18,38.3 v2(49.93,38.55)
DDR3_CK_P: length 31.5
  TOP w0.127: U2.J7 v2(54.42,51.07) ; U4.N3 v2(49.93,37.75)
  BOTTOM w0.127: v2(49.93,37.75) 50.2,38.02 50.41,38.02 51.23,38.84 51.23,41.78 49.4,43.62 49.4,44.15 50.03,44.78 50.7,44.78 51.87,43.61 54.18,43.61 54.6,44.03 54.6,45.09 54.97,45.46 58.94,45.46 59.42,45.94 59.42,46.66 58.91,47.18 55.21,47.18 54.7,47.69 54.7,50.38 54.42,50.66 v2(54.42,51.07) 54.42,51.47 R142.1
DDR3_CKE: length 34.9
  TOP w0.165: U4.L3 v2(51.53,37.75) ; v2(53.62,48.67) U2.K9
  L6_SIG w0.165: v2(53.62,48.67) 53.62,46.24 53.29,45.92 50.99,45.92 50.53,45.45 50.53,45.15 50.73,44.95 51.03,44.95 51.32,45.24 52.93,45.24 53.13,45.05 53.13,44.77 52.93,44.57 51.73,44.57 51.53,44.37 51.53,44.09 51.73,43.9 53.28,43.9 53.43,43.75 53.43,43.38 53.28,43.22 52.3,43.22 52.13,43.05 52.13,42.75 52.33,42.55 53,42.55 53.13,42.42 53.13,42.01 53,41.88 52.13,41.88 51.93,41.68 51.93,41.4 52.13,41.21 52.53,41.21 52.73,41.01 52.73,40.72 52.53,40.52 52.33,40.52 52.13,40.32 52.13,40.04 52.33,39.85 53.38,39.85 53.64,39.58 53.64,39.2 53.4,38.96 51.02,38.96 50.86,38.79 50.86,38.52 51.03,38.35 52.64,38.35 52.83,38.15 53.41,38.15 53.63,37.93 53.63,37.58 53.4,37.35 U4.L3 v2(51.53,37.75)
  BOTTOM w0.165: v2(53.62,48.67) 53.82,48.47 53.82,48.07 53.63,47.88 R38.1
DDR3_CS#: length 29.4
  TOP w0.165: v2(43.92,39.95) 45.63,39.95 46.32,39.25 47.33,39.25 48.44,38.15 U4.R2 ; U2.L2 v2(52.82,55.07)
  L6_SIG w0.165: v2(52.82,55.07) 52.23,54.67 51.01,54.67 50.82,54.48 50.82,53.78 48.11,51.07 46.31,51.07 42.92,47.68 42.92,40.95 v2(43.92,39.95)
  BOTTOM w0.165: v2(52.82,55.07) 53.09,55.07 53.22,55.2 53.22,56.15 R39.1
DDR3_DM0: length 26.5
  TOP w0.165: v2(59.22,52.67) 59.22,51.87 U2.E7 ; U4.B1 60.01,39.82 62.25,39.82 v2(63.13,38.95)
  L6_SIG w0.165: v2(59.22,52.67) 59.62,52.27 62.63,52.27 63.52,51.37 63.52,50.49 63.2,50.16 63.2,49.89 63.4,49.69 63.68,49.69 63.9,49.91 64.18,49.91 64.53,49.56 64.53,40.35 v2(63.13,38.95)
DDR3_DM1: length 23.1
  TOP w0.165: v2(59.22,53.47) U2.D3 ; U4.D3 v2(57.93,37.75)
  L5_SIG w0.165: v2(57.93,37.75) 57.53,37.35 54.42,37.35 54.23,37.55 54.23,40.95 55.63,42.35 55.63,45.78 58.02,48.16 58.02,50.54 58.52,51.05 58.52,52.78 v2(59.22,53.47)
DDR3_DQ0: length 28.4
  TOP w0.165: U4.D4 v2(57.93,36.95) ; U2.E3 58.42,54.27 v2(58.42,54.27)
  L6_SIG w0.165: v2(57.93,36.95) 58.33,36.55 61.23,36.55 62.63,37.95 62.63,39.15 64.13,40.65 64.13,47.76 63.79,48.1 63.79,48.38 63.96,48.55 63.96,48.83 63.76,49.02 63.48,49.02 63.31,48.85 63.03,48.85 62.63,49.26 62.63,50.76 61.92,51.47 59.72,51.47 58.77,52.42 58.77,53.67 58.99,53.88 58.99,54.09 58.81,54.27 v2(58.42,54.27)
DDR3_DQ1: length 24.7
  TOP w0.165: U4.A2 61.73,38.15 v2(62.13,38.55) ; U2.F7 57.22,51.47 v2(58.02,52.27)
  L6_SIG w0.165: v2(58.02,52.27) 59.62,50.67 61.92,50.67 62.12,50.47 62.12,48.6 62.29,48.43 62.77,48.43 62.93,48.26 62.93,47.93 62.77,47.77 62.24,47.77 62.07,47.6 62.07,47.27 62.24,47.11 63.47,47.11 63.63,46.94 63.63,40.97 63.32,40.66 62.72,40.66 62.13,40.07 v2(62.13,38.55)
DDR3_DQ2: length 23.2
  TOP w0.165: U4.C4 v2(58.73,36.95) ; U2.F2 v2(56.82,55.07)
  L6_SIG w0.165: v2(58.73,36.95) 58.33,37.35 56.94,37.35 56.73,37.56 56.73,39.05 55.13,40.65 55.13,41.15 54.73,41.55 54.73,43.15 54.41,43.47 54.41,49.87 54.82,50.27 54.82,53.68 55.81,54.67 56.42,54.67 v2(56.82,55.07)
DDR3_DQ3: length 28.4
  TOP w0.165: v2(58.02,51.47) 57.62,51.07 57.62,50.27 U2.F8 ; U4.C1 60.03,40.65 v2(61.63,40.65)
  L6_SIG w0.165: v2(58.02,51.47) 58.02,51.37 59.33,50.06 60.33,50.06 60.53,49.86 60.53,49 60.69,48.84 60.98,48.84 61.15,48.67 61.15,48.34 60.98,48.18 60.69,48.18 60.53,48.01 60.53,47.45 61.35,46.63 62.93,46.63 63.13,46.43 63.13,46.13 62.89,45.89 61.65,45.89 61.42,45.66 61.42,45.36 61.62,45.16 62.97,45.16 63.14,44.99 63.14,44.66 62.97,44.5 62.2,44.5 62.03,44.33 62.03,44 62.2,43.84 62.97,43.84 63.14,43.67 63.14,43.34 62.97,43.18 62.4,43.18 62.23,43.01 62.23,42.68 62.4,42.52 62.97,42.52 63.14,42.35 63.14,42.02 62.97,41.86 62.4,41.86 62.23,41.69 62.23,41.25 v2(61.63,40.65)
DDR3_DQ4: length 21.8
  TOP w0.165: v2(59.53,36.95) U4.B4 ; v2(56.83,52.66) 55.62,53.87 U2.H3
  L6_SIG w0.165: v2(59.53,36.95) 59.93,37.35 60.93,37.35 61.34,37.76 61.34,39.34 60.53,40.15 60.53,45.05 60.22,45.37 59.82,45.37 59.52,45.67 59.52,46.06 58.02,47.57 58.02,50.77 57.62,51.17 57.62,52.47 57.43,52.66 v2(56.83,52.66)
DDR3_DQ5: length 22.8
  TOP w0.165: v2(58.42,47.87) 57.02,47.87 56.02,48.87 56.02,49.47 U2.H8 ; v2(60.33,36.95) U4.A4
  L6_SIG w0.165: v2(58.42,47.87) 58.82,48.27 58.82,48.52 58.96,48.67 59.32,48.67 59.47,48.52 59.47,47.91 59.02,47.47 59.02,47.27 59.99,46.3 60.22,46.3 60.45,46.54 60.69,46.54 60.92,46.3 60.92,46.07 60.69,45.83 60.69,45.6 61.03,45.26 61.03,44.92 61.19,44.76 61.52,44.76 61.69,44.59 61.69,44.26 61.52,44.1 61.19,44.1 61.03,43.93 61.03,41.98 61.19,41.82 61.52,41.82 61.69,41.65 61.69,41.32 61.52,41.16 61.19,41.16 61.03,40.99 61.03,40.35 61.73,39.65 61.73,37.65 61.03,36.95 v2(60.33,36.95)
DDR3_DQ6: length 23.9
  TOP w0.165: U2.G2 v2(56.02,54.27) ; U4.C3 v2(58.73,37.75)
  L6_SIG w0.165: v2(58.73,37.75) 58.33,38.15 57.63,38.15 57.53,38.26 57.53,39.51 57.52,39.52 57.52,39.86 57.12,40.26 56.22,40.26 55.63,40.85 55.63,43.43 55.31,43.76 54.94,43.76 54.81,43.89 54.81,44.29 55.01,44.49 55.62,44.49 55.81,44.69 55.81,44.97 55.62,45.16 55.01,45.16 54.81,45.36 54.81,45.64 55.01,45.84 55.22,45.84 55.41,46.03 55.41,46.31 55.22,46.51 55.01,46.51 54.81,46.71 54.81,46.99 55.01,47.18 55.22,47.18 55.41,47.38 55.41,47.77 55.22,47.97 55.02,47.97 54.81,48.17 54.81,49.67 55.23,50.09 55.23,53.49 v2(56.02,54.27)
DDR3_DQ7: length 21.8
  TOP w0.165: U2.H7 55.62,50.67 v2(56.82,51.87) ; U4.A3 v2(60.34,37.75)
  L6_SIG w0.165: v2(60.34,37.75) 60.73,37.75 60.83,37.85 60.83,38.15 59.53,39.45 59.53,40.47 59.73,40.67 59.83,40.67 60.03,40.86 60.03,41.14 59.83,41.34 59.73,41.34 59.53,41.54 59.53,41.82 59.73,42.01 59.83,42.01 60.03,42.21 60.03,42.49 59.83,42.69 59.73,42.69 59.53,42.88 59.53,44.16 58.59,45.1 58.59,45.38 58.91,45.69 58.91,45.97 58.71,46.17 58.43,46.17 58.11,45.85 57.93,45.85 57.73,46.06 57.73,47.15 57.47,47.41 56.88,47.41 56.72,47.57 56.72,47.87 56.94,48.09 57.09,48.09 57.22,48.21 57.22,49.07 57.52,49.37 57.52,50.57 57.22,50.88 57.22,51.47 v2(56.82,51.87)
DDR3_DQ8: length 28.2
  TOP w0.165: v2(60.02,52.67) 59.62,52.27 59.62,51.47 U2.D7 ; v2(57.13,39.35) 57.13,39.35 56.73,38.95 U4.E1
  L5_SIG w0.165: v2(60.02,52.67) 60.42,52.27 60.42,51.67 60.62,51.47 60.99,51.47 61.23,51.71 61.23,52.38 61.5,52.66 62.63,52.66 63.35,51.94 63.35,51.56 62.92,51.13 62.92,50.87 63.11,50.68 63.44,50.68 63.62,50.87 64.02,50.87 64.22,50.67 64.22,41.86 62.12,39.76 57.54,39.76 v2(57.13,39.35)
DDR3_DQ9: length 25.8
  TOP w0.165: v2(60.02,53.47) U2.C3 ; v2(57.13,38.55) U4.D1
  L5_SIG w0.165: v2(57.13,38.55) 57.63,39.05 59.83,39.05 60.03,38.85 60.63,38.85 61.14,39.36 62.32,39.36 64.92,41.96 64.92,49.59 64.62,49.89 64.62,50.25 64.72,50.35 64.72,51.17 62.52,53.37 62.22,53.37 61.91,53.06 60.43,53.06 v2(60.02,53.47)
DDR3_DQ10: length 28.6
  TOP w0.165: U2.C8 60.01,50.26 v2(61.62,50.26) ; v2(57.03,41.05) 57.03,40.05 56.33,39.35 56.33,38.55 U4.E2
  L5_SIG w0.165: v2(61.62,50.26) 62.12,49.77 62.12,48.67 62.34,48.45 63.24,48.45 63.42,48.27 63.42,47.04 63.22,46.85 62.82,46.85 62.62,46.65 62.62,46.37 62.82,46.17 63.22,46.17 63.42,45.98 63.42,45.7 63.22,45.5 63.02,45.5 62.82,45.3 62.82,45.02 63.34,44.51 63.34,44.18 62.46,43.3 62.46,42.92 63.14,42.25 63.14,41.98 62.54,41.39 62.25,41.39 62.02,41.62 62.02,42.52 61.88,42.66 61.32,42.66 61.12,42.46 61.12,41.86 61.52,41.46 61.52,41.24 61.03,40.75 60.44,40.75 60.22,40.96 59.82,40.96 59.61,40.75 58.76,40.75 58.63,40.88 58.63,41.55 58.13,42.05 57.73,42.05 57.33,41.65 57.33,41.35 v2(57.03,41.05)
DDR3_DQ11: length 27
  TOP w0.165: v2(60.02,54.27) U2.C2 ; v2(57.13,37.75) U4.E3
  L5_SIG w0.165: v2(57.13,37.75) 57.53,38.15 60.61,38.15 61.41,38.95 62.51,38.95 65.32,41.76 65.32,51.27 62.32,54.27 v2(60.02,54.27)
DDR3_DQ12: length 29.5
  TOP w0.165: v2(56.33,37.75) U4.F3 ; v2(61.62,51.07) U2.A7
  L5_SIG w0.165: v2(56.33,37.75) 56.33,39.36 57.53,40.56 57.53,41.05 57.73,41.25 57.97,41.25 58.13,41.09 58.13,40.42 58.39,40.16 61.92,40.16 63.82,42.07 63.82,42.56 63.6,42.78 63.32,42.78 63.12,42.98 63.12,43.26 63.32,43.46 63.61,43.46 63.82,43.66 63.82,48.77 63.65,48.94 62.82,48.94 62.62,49.14 62.62,49.42 62.82,49.61 63.6,49.61 63.82,49.84 63.82,50.07 63.59,50.3 62.39,50.3 62.19,50.5 62.19,50.94 62.72,51.47 62.72,51.78 62.23,52.26 61.83,52.26 61.62,52.05 v2(61.62,51.07)
DDR3_DQ13: length 28.8
  TOP w0.165: v2(55.13,42.45) 55.13,39.85 55.01,39.49 55.01,39.31 U4.G1 ; v2(61.62,55.07) U2.A2
  L5_SIG w0.165: v2(61.62,55.07) 61.22,55.47 55.02,55.47 54.62,55.07 54.62,54.74 55.03,54.32 55.03,50.69 54.82,50.47 54.42,50.47 54.13,50.18 54.13,47.96 54.34,47.75 55.33,47.75 55.61,47.47 55.61,47.16 55.32,46.86 54.11,46.86 53.93,46.68 53.93,45.85 54.22,45.56 54.22,42.47 54.59,42.09 54.77,42.09 v2(55.13,42.45)
DDR3_DQ14: length 28.5
  TOP w0.165: U2.B8 60.82,49.47 60.82,48.67 v2(60.02,47.87) ; v2(54.73,40.65) 54.35,40.27 54.35,38.97 U4.H1
  L5_SIG w0.165: v2(54.73,40.65) 54.73,40.95 56.62,42.84 56.62,43.17 56.82,43.37 57.15,43.37 57.32,43.54 57.32,43.77 57.11,43.97 56.26,43.97 56.03,44.2 56.03,44.52 56.26,44.75 58.52,44.75 58.72,44.94 58.72,45.22 58.47,45.47 56.77,45.47 56.54,45.7 56.54,45.93 56.77,46.17 57.33,46.17 57.53,46.37 57.53,47.17 57.72,47.37 58.02,47.37 58.22,47.17 58.22,46.37 58.42,46.17 58.62,46.17 58.82,46.37 58.82,50.17 58.98,50.33 59.26,50.33 59.42,50.17 59.42,47.7 59.54,47.58 59.72,47.58 v2(60.02,47.87)
DDR3_DQ15: length 31.7
  TOP w0.165: U4.H2 53.95,38.53 53.95,40.97 54.73,41.75 54.73,42.75 v2(55.13,43.15) ; v2(61.62,53.47) U2.A3
  L5_SIG w0.165: v2(55.13,43.15) 54.63,43.65 54.63,46.08 54.82,46.27 55.42,46.27 56.42,47.27 56.42,47.67 55.82,48.27 54.84,48.27 54.63,48.48 54.63,49.58 55,49.96 55.53,49.96 56.41,49.07 57.12,49.07 57.32,49.27 57.32,51.27 57.12,51.47 56.42,51.47 55.43,52.46 55.43,54.46 55.64,54.67 58.91,54.67 59.71,53.87 U2.A3 v2(61.62,53.47)
DDR3_DQS0_N: length 24.1
  TOP w0.127: v2(56.82,53.47) 56.82,53.47 U2.G3 ; U4.B2 v2(59.53,38.55)
  L6_SIG w0.14: v2(59.53,38.55) 59.05,39.03 59.05,41.49 58.67,41.87 57.02,41.87 56.83,42.06 56.83,42.33 57.02,42.51 58.67,42.51 59.05,42.89 59.05,43.84 58.36,44.52 57.92,44.52 57.19,43.78 56.95,43.78 56.58,44.15 56.58,44.33 57.3,45.05 57.3,45.58 56.22,46.66 56.22,53.22 56.47,53.47 v2(56.82,53.47)
DDR3_DQS0_P: length 24.6
  TOP w0.127: U2.F3 v2(56.82,54.27) ; U4.C2 v2(58.73,38.55)
  L6_SIG w0.14: v2(58.73,38.55) 58.73,41.36 58.54,41.55 56.89,41.55 56.52,41.93 56.52,42.46 56.89,42.83 58.54,42.83 58.73,43.02 58.73,43.7 58.23,44.2 58.05,44.2 57.32,43.47 56.82,43.47 56.26,44.02 56.26,44.46 56.98,45.18 56.98,45.45 55.9,46.53 55.9,53.35 v2(56.82,54.27)
DDR3_DQS1_N: length 28.1
  TOP w0.127: v2(60.82,51.07) U2.B7 ; U4.F2 v2(55.53,38.55)
  L5_SIG w0.14: v2(60.82,51.07) 60.34,50.59 60.34,50.3 60.94,49.7 60.94,48.4 61.16,48.17 61.86,48.17 62.32,47.71 62.32,47.07 61.91,46.66 60.46,46.66 60.24,46.43 60.24,46.11 60.46,45.89 61.71,45.89 62.2,45.39 62.2,43.95 61.8,43.55 60.83,43.55 59.91,44.48 59.5,44.48 59.13,44.1 59.13,43.83 60.3,42.65 60.3,42.07 59.89,41.65 59.3,41.65 58.13,42.83 57.76,42.83 55.63,40.71 55.63,40.23 55.05,39.64 55.05,38.87 55.16,38.76 55.32,38.76 v2(55.53,38.55)
DDR3_DQS1_P: length 27.7
  TOP w0.127: U4.G2 v2(54.73,38.55) ; U2.C7 v2(60.02,51.07)
  L5_SIG w0.14: v2(54.73,38.55) 54.73,39.77 55.31,40.36 55.31,40.84 57.63,43.15 58.26,43.15 59.44,41.97 59.76,41.97 59.98,42.2 59.98,42.52 58.81,43.7 58.81,44.23 59.37,44.79 60.04,44.79 60.96,43.87 61.67,43.87 61.89,44.08 61.89,45.26 61.58,45.57 60.33,45.57 59.92,45.98 59.92,46.56 60.33,46.98 61.78,46.98 62.01,47.2 62.01,47.57 61.72,47.85 61.03,47.85 60.62,48.27 60.62,49.57 60.02,50.17 v2(60.02,51.07)
DDR3_ODT: length 36.8
  TOP w0.165: U4.K3 v2(52.33,37.75) ; U2.K1 v2(53.62,55.87)
  L5_SIG w0.165: v2(52.33,37.75) 52.33,39.75 52.13,39.95 51.73,39.95 51.53,40.15 51.53,41.46 51.73,41.66 51.93,41.66 52.13,41.86 52.13,43.25 51.23,44.15 51.23,47.46 51.63,47.86 51.63,48.16 51.32,48.47 51.32,48.84 51.55,49.07 52.34,49.07 52.73,49.46 52.73,50.26 52.2,50.79 52.2,51.38 52.4,51.58 53.97,51.58 54.33,51.94 54.33,52.85 54.02,53.16 54.02,55.55 54.98,56.51 58.09,56.51 58.34,56.76 58.34,57.06 58.04,57.36 53.9,57.36 53.61,57.07 53.61,55.87 v2(53.62,55.87)
  BOTTOM w0.165: R33.1 54.32,55.6 54.19,55.47 54.01,55.47 v2(53.62,55.87)
DDR3_RAS#: length 28.5
  TOP w0.165: v2(48.22,34.95) 48.73,34.95 U4.R6 ; U2.J3 v2(54.42,53.47)
  L6_SIG w0.165: v2(48.22,34.95) 47.72,35.45 47.72,37.76 50.33,40.38 50.33,42.25 49.62,42.96 48.82,42.96 48.53,43.25 48.53,45.58 50.22,47.27 51.02,47.27 51.62,47.87 51.62,51.15 52.42,51.94 52.42,52.97 53.32,53.87 54.02,53.87 v2(54.42,53.47)
  BOTTOM w0.165: R37.1 53.13,53.86 54.03,53.86 v2(54.42,53.47)
DDR3_RST#: length 29.2
  TOP w0.165: U4.L4 v2(51.53,36.95) ; U2.T2 48.02,55.87 v2(47.62,55.87)
  L5_SIG w0.165: v2(44.32,52.02) 44.68,52.02 47.62,54.96 v2(47.62,55.87)
  BOTTOM w0.165: v2(47.62,55.87) 47.62,56.18 R42.1 ; v2(51.53,36.95) 51.13,36.55 48.85,36.55 44.61,40.79 44.61,42.46 44.32,42.76 v2(44.32,52.02)
DDR3_WE#: length 28.9
  TOP w0.165: U2.L3 v2(53.62,54.27) ; U4.R3 46.93,37.35 46.31,37.96 45.91,37.96 v2(45.61,38.26)
  L6_SIG w0.165: v2(45.61,38.26) 45.61,44.96 45.4,45.17 44.91,45.17 44.71,45.37 44.71,46.77 44.91,46.97 46.01,46.97 46.31,47.27 46.71,47.27 47.01,46.97 47.51,46.97 48.41,47.87 48.41,49.57 49.91,51.07 49.91,51.77 51.6,53.46 51.93,53.46 53.03,54.56 53.33,54.56 v2(53.62,54.27)
  BOTTOM w0.165: v2(53.62,54.27) 53.22,54.67 52.66,54.67 52.54,54.54 R31.1
EN_DAT_USB: length 17
  TOP w0.127: U8.6 92.29,60.3 v1(92.31,60.28)
  BOTTOM w0.127: R72.1 93.95,61.54 92.7,60.28 v1(92.31,60.28) 92.31,58.12 92.15,57.96 89.91,57.96 89,58.87 89,64.08 89.48,64.56 R71.2
EN_POW_USB: length 5.3
  TOP w0.127: v1(90.79,59.89) U8.3
  BOTTOM w0.127: v1(90.79,59.89) 90.79,60.36 R70.2 89.63,61.52 89.63,63.47 R71.1
FB0: length 5.9
  TOP w0.305: U3.4 v1(88.11,22.55)
  BOTTOM w0.305: R4.1 85.7,21.13 85.7,22.68 86.35,23.33 R2.2 v1(88.11,22.55)
FB_1P8V: length 13.7
  TOP w0.203: v1(94.71,41.48) 94.37,41.82 U6.32
  BOTTOM w0.203: v1(94.71,41.48) 94.07,41.48 R65.2 88,41.36 84.68,38.05 R64.1
FB_1P35V: length 11.7
  TOP w0.305: U6.9 94.62,46.72 v1(94.84,46.94)
  BOTTOM w0.203: R63.1 94.84,46.24 v1(94.84,46.94) 94.84,47.95 94.08,48.71 88.36,48.71 87.98,49.1 R62.2
IO_02_34_AD9361_CLKOUT: length 27.2
  TOP w0.102: U4.P8 49.13,33.75 47.83,33.75 v2(47.43,33.35) ; U5.J6 v2(27.55,32.88)
  L6_SIG w0.114: v2(27.55,32.88) 27.95,33.28 28.55,33.28 28.75,33.48 28.75,33.88 28.95,34.08 29.35,34.08 29.55,34.28 29.55,35.55 30.47,36.48 43.1,36.48 45.73,33.85 46.92,33.85 v2(47.43,33.35)
  BOTTOM w0.102: AD9361_CLKOUT.1 v2(27.55,32.88)
IO_02_34_AD9361_RST: length 31.6
  TOP w0.102: U4.P9 49.13,32.95 47.82,32.95 v2(47.43,32.55) ; U5.K5 v2(26.74,33.68)
  L5_SIG w0.114: v2(47.43,32.55) 47.83,32.95 47.83,33.63 47.34,34.11 46.33,34.11 40.87,39.57 31.21,39.57 29.57,37.93 28.68,37.93 27.14,36.39 27.14,34.08 v2(26.74,33.68)
IO_L01_34_FB_CLK: length 27.6
  TOP w0.102: U4.P10 49.13,31.34 47.93,31.34 v2(47.53,30.95) ; U5.F10 v2(30.74,28.88)
  L6_SIG w0.114: v2(30.74,28.88) 31.15,28.48 31.15,26.81 32.36,25.6 35.15,25.6 35.38,25.83 35.46,25.83 35.47,25.84 37.04,25.84 37.29,25.6 42.78,25.6 42.91,25.47 43.4,25.47 43.52,25.6 46.07,25.6 47.15,26.67 47.4,26.67 47.96,27.23 47.96,28.48 48.26,28.78 48.26,30.22 v2(47.53,30.95)
IO_L01_34_RX_D0: length 49.9
  TOP w0.102: v2(54.73,28.15) U4.H14 ; v2(26.74,28.08) U5.K11
  L5_SIG w0.114: v2(54.73,28.15) 54.73,27.75 54.83,27.65 54.83,23.69 51.56,20.41 43.39,20.41 43,20.8 39.95,20.8 39.6,21.16 37.56,21.16 37.18,21.54 36.94,21.54 36.8,21.4 36.8,20.67 36.65,20.52 36.45,20.52 36.3,20.67 36.3,21.39 36.16,21.54 35.7,21.54 35.56,21.68 35.56,22.03 35.41,22.17 35.21,22.17 35.06,22.03 35.06,21.68 34.92,21.54 34.71,21.54 34.57,21.68 34.57,22.03 34.42,22.17 34.22,22.17 34.07,22.03 34.07,21.68 33.93,21.54 33.72,21.54 33.58,21.68 33.58,22.03 33.43,22.17 33.23,22.17 33.08,22.03 33.08,21.68 32.94,21.54 32.73,21.54 32.59,21.68 32.59,22.03 32.44,22.17 32.23,22.17 32.09,22.03 32.09,21.68 31.94,21.54 31.74,21.54 31.59,21.68 31.59,22.03 31.45,22.17 31.24,22.17 31.1,22.03 31.1,21.68 30.95,21.54 30.75,21.54 30.6,21.68 30.6,22.03 30.46,22.17 30.25,22.17 30.11,22.03 30.11,21.68 29.96,21.54 29.69,21.54 26.77,24.46 26.77,24.93 26.62,25.07 26.15,25.07 26.01,25.22 26.01,25.42 26.15,25.57 26.62,25.57 26.77,25.71 26.77,25.98 26.57,26.19 26.03,26.19 25.88,26.33 25.88,26.54 26.03,26.68 26.2,26.68 26.34,26.82 26.34,27.68 v2(26.74,28.08)
IO_L01_34_RX_D1: length 49.3
  TOP w0.102: v2(27.54,27.28) 27.55,27.28 U5.J12 ; v2(53.93,28.94) U4.J13
  L5_SIG w0.114: v2(53.93,28.94) 53.93,28.15 53.53,27.75 53.53,23.66 51.03,21.16 43.41,21.16 43.28,21.29 40.48,21.29 40.23,21.54 40.23,21.69 40.54,21.99 40.54,22.25 40.33,22.45 40.13,22.45 39.64,21.97 39.46,21.97 39.3,22.13 39.3,22.32 39.78,22.8 39.78,23.01 39.63,23.15 39.43,23.15 38.97,22.7 38.76,22.7 38.62,22.84 38.62,23.05 39.08,23.5 39.08,23.71 38.93,23.85 38.74,23.85 38.19,23.3 37.96,23.3 37.82,23.44 37.82,24.08 37.69,24.2 37.32,24.2 37.17,24.06 37.17,23.71 37.03,23.57 36.79,23.57 36.64,23.71 36.64,24.06 36.5,24.2 36.29,24.2 36.15,24.06 36.15,23.71 36.04,23.61 35.76,23.61 35.65,23.71 35.65,24.06 35.51,24.2 35.3,24.2 35.16,24.06 35.16,23.71 35.01,23.57 34.81,23.57 34.66,23.71 34.66,23.98 34.56,24.09 34.28,24.09 34.17,23.98 34.17,23.71 34.02,23.57 33.82,23.57 33.67,23.71 33.67,24.06 33.53,24.2 33.32,24.2 33.18,24.06 33.18,23.71 33.03,23.57 32.83,23.57 32.68,23.71 32.68,24.06 32.54,24.2 32.33,24.2 32.19,24.06 32.19,23.71 32.04,23.57 31.84,23.57 31.69,23.71 31.69,24.06 31.55,24.2 31.34,24.2 31.2,24.06 31.2,23.68 31.09,23.57 30.84,23.57 30.7,23.71 30.7,24.06 30.55,24.2 30.35,24.2 30.2,24.06 30.2,23.71 30.06,23.57 28.97,23.57 27.54,25 v2(27.54,27.28)
IO_L02_34_RX_D2: length 50.6
  TOP w0.102: U5.K10 v2(26.74,28.88) ; v2(55.53,28.15) U4.G14
  L5_SIG w0.114: v2(26.74,28.88) 26.35,29.27 25.74,29.27 25.54,29.07 25.54,28.75 25.3,28.51 24.98,28.51 24.48,28.01 24.48,26.62 24.99,26.11 24.99,25.73 24.74,25.47 24.74,25.09 29.06,20.77 31.24,20.77 31.38,20.63 31.38,20.03 31.53,19.89 31.73,19.89 31.88,20.03 31.88,20.63 32.02,20.77 32.23,20.77 32.37,20.63 32.37,20.03 32.52,19.89 32.72,19.89 32.87,20.03 32.87,20.63 33.01,20.77 33.37,20.77 33.5,20.65 33.5,20.01 33.88,19.63 52.04,19.63 55.93,23.52 55.93,27.75 v2(55.53,28.15)
IO_L02_34_RX_D3: length 49.1
  TOP w0.102: U4.H13 v2(54.73,28.95) ; v2(27.54,28.07) U5.J11
  L5_SIG w0.114: v2(54.73,28.95) 54.23,28.45 54.23,27.95 53.93,27.65 53.93,23.42 51.28,20.77 43.41,20.77 43.14,21.05 40.24,21.05 39.77,21.51 38.66,21.51 38.25,21.92 38.25,22.68 38.05,22.88 37.79,22.88 37.59,22.68 37.59,22.07 37.44,21.92 37.23,21.92 37.08,22.07 37.08,22.83 36.93,22.98 36.63,22.98 36.45,22.81 36.45,22.1 36.27,21.92 36.09,21.92 35.94,22.06 35.94,22.41 35.8,22.55 35.29,22.55 35.14,22.7 35.14,23.04 35,23.19 34.79,23.19 34.65,23.04 34.65,22.7 34.5,22.55 34.3,22.55 34.15,22.7 34.15,23.04 34.01,23.19 33.8,23.19 33.66,23.04 33.66,22.7 33.51,22.55 33.31,22.55 33.16,22.7 33.16,23.04 33.02,23.19 32.81,23.19 32.67,23.04 32.67,22.7 32.52,22.55 32.32,22.55 32.17,22.7 32.17,23.04 32.03,23.19 31.87,23.19 31.68,23 31.68,22.7 31.53,22.55 31.33,22.55 31.18,22.7 31.18,23.04 31.04,23.19 30.83,23.19 30.69,23.04 30.69,22.7 30.54,22.55 30.34,22.55 30.19,22.7 30.19,23.04 30.05,23.19 29.84,23.19 29.7,23.04 29.7,22.7 29.55,22.55 29.31,22.55 27.15,24.71 27.15,27.68 v2(27.54,28.07)
IO_L03_34_RX_D4: length 51.7
  TOP w0.102: U4.G12 v2(55.53,29.75) ; U5.K9 v2(26.74,29.68)
  L5_SIG w0.114: v2(26.74,29.68) 26.35,30.07 24.93,30.07 24.23,29.37 24.23,25.09 29.94,19.38 52.42,19.38 56.73,23.68 56.73,27.35 55.93,28.15 55.93,29.14 55.73,29.35 55.6,29.35 55.53,29.42 v2(55.53,29.75)
IO_L03_34_RX_D5: length 50.6
  TOP w0.102: U5.J10 v2(27.55,28.88) ; U4.H12 v2(54.73,29.75)
  L5_SIG w0.114: v2(27.55,28.88) 27.54,28.88 27.14,28.47 25.74,28.47 25.5,28.23 25.5,25.09 29.44,21.16 33.74,21.16 33.89,21.01 33.89,20.28 34.03,20.14 34.24,20.14 34.38,20.28 34.38,21.01 34.53,21.16 34.73,21.16 34.88,21.01 34.88,20.28 35.02,20.14 35.23,20.14 35.37,20.28 35.37,21.01 35.52,21.16 35.79,21.16 35.91,21.03 35.91,20.27 36.04,20.14 36.93,20.14 37.56,20.77 39.6,20.77 39.81,20.56 42.86,20.56 43.41,20.01 51.79,20.01 55.13,23.35 55.13,29.35 v2(54.73,29.75)
IO_L04_34_RX_D6: length 55.1
  TOP w0.102: U4.G11 v2(55.53,30.55) ; U5.K8 v2(26.74,30.48)
  L5_SIG w0.114: v2(26.74,30.48) 26.29,30.93 25.37,30.93 23.98,29.54 23.98,24.84 29.69,19.12 52.8,19.12 57.53,23.85 57.53,27.39 57.27,27.65 57.03,27.65 56.73,27.95 56.73,29.15 56.53,29.35 56.13,29.35 55.93,29.55 55.93,30.15 v2(55.53,30.55)
